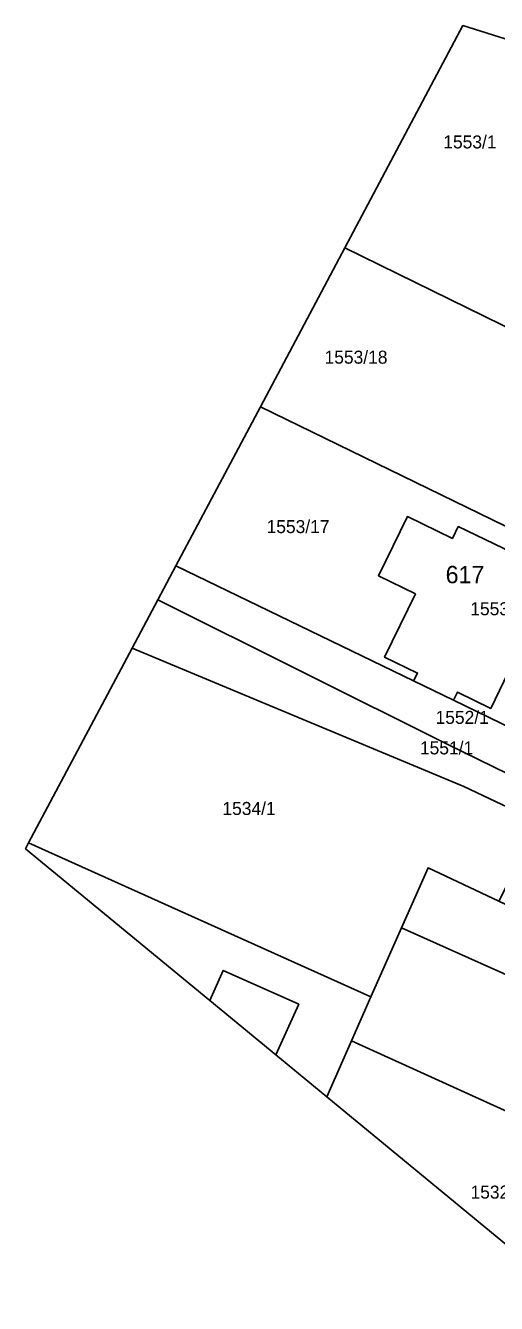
# Model space of a CAD drawing. Extents: x -559813 to -559493, y -1075874 to -1075701.
# Drawn here: x -559812.9 to -559758.6, y -1075848.7 to -1075701.4 of the extents above; entities that cross this region are included whole.
import ezdxf

# ---------------------------------------------------------------- set-up
doc = ezdxf.new("R2010")
doc.units = 0
for name, color, linetype in [('Adresní místo-text', 7, 'Continuous'), ('Parcela-polygon', 7, 'Continuous'), ('Parcela-text', 7, 'Continuous')]:
    doc.layers.add(name, color=color, linetype=linetype)

msp = doc.modelspace()

# ---------------------------------------------------------------- linework, layer by layer
at = {"layer": 'Parcela-polygon'}
for p, q in [((-559776.1, -1075727), (-559785.83, -1075745.32)), ((-559785.83, -1075745.32), (-559795.59, -1075763.68)), ((-559795.59, -1075763.68), (-559797.67, -1075767.59)), ((-559797.67, -1075767.59), (-559800.61, -1075773.14)), ((-559800.61, -1075773.14), (-559812.55, -1075795.61)), ((-559791.68, -1075813.75), (-559784.05, -1075820.04)), ((-559784.05, -1075820.04), (-559778.19, -1075824.87)), ((-559778.19, -1075824.87), (-559749.28, -1075848.69))]:
    msp.add_line(p, q, dxfattribs=at)
for points in [[(-559733.58, -1075710.47), (-559762.5, -1075701.39), (-559776.1, -1075727)], [(-559776.1, -1075727), (-559731.8, -1075748.76), (-559730.08, -1075745.15), (-559717.64, -1075718.96), (-559733.14, -1075710.71), (-559733.58, -1075710.47)], [(-559785.83, -1075745.32), (-559747.18, -1075764.18), (-559737.76, -1075760.91), (-559731.8, -1075748.76), (-559776.1, -1075727)], [(-559795.59, -1075763.68), (-559768.2, -1075776.93), (-559767.73, -1075776.03), (-559771.54, -1075774.2), (-559767.99, -1075766.9), (-559772.22, -1075764.81), (-559768.9, -1075757.99), (-559763.72, -1075760.51), (-559763.04, -1075759.14), (-559751.73, -1075764.6), (-559753.61, -1075768.39), (-559752.72, -1075768.82), (-559754.91, -1075773.41), (-559755.83, -1075772.92), (-559759.31, -1075780.1), (-559763.15, -1075778.22), (-559763.6, -1075779.15), (-559749.98, -1075785.74), (-559743.97, -1075773.56), (-559747.18, -1075764.18), (-559785.83, -1075745.32)], [(-559797.67, -1075767.59), (-559764.23, -1075784.25), (-559752.15, -1075790.16), (-559749.98, -1075785.74), (-559763.6, -1075779.15), (-559768.2, -1075776.93), (-559795.59, -1075763.68)], [(-559800.61, -1075773.14), (-559762.4, -1075789.09), (-559753.71, -1075793.22), (-559752.15, -1075790.16), (-559764.23, -1075784.25), (-559797.67, -1075767.59)], [(-559812.55, -1075795.61), (-559773.1, -1075813.33), (-559769.59, -1075805.38), (-559766.53, -1075798.46), (-559758.36, -1075802.33), (-559753.71, -1075793.22), (-559762.4, -1075789.09), (-559800.61, -1075773.14)], [(-559812.55, -1075795.61), (-559812.9, -1075796.28), (-559791.68, -1075813.75)], [(-559778.19, -1075824.87), (-559775.35, -1075818.43), (-559773.1, -1075813.33), (-559812.55, -1075795.61)], [(-559791.68, -1075813.75), (-559790.13, -1075810.29), (-559781.43, -1075814.2), (-559784.05, -1075820.04)], [(-559784.05, -1075820.04), (-559781.43, -1075814.2), (-559790.13, -1075810.29), (-559791.68, -1075813.75)], [(-559749.28, -1075848.69), (-559748.24, -1075846.45), (-559755.02, -1075843.27), (-559749.7, -1075831.92), (-559742.95, -1075835.07), (-559742.2, -1075833.46), (-559775.35, -1075818.43), (-559778.19, -1075824.87)]]:
    msp.add_lwpolyline(points, dxfattribs=at)
for points in [[(-559763.72, -1075760.51), (-559768.9, -1075757.99), (-559772.22, -1075764.81), (-559767.99, -1075766.9), (-559771.54, -1075774.2), (-559767.73, -1075776.03), (-559768.2, -1075776.93), (-559763.6, -1075779.15), (-559763.15, -1075778.22), (-559759.31, -1075780.1), (-559755.83, -1075772.92), (-559754.91, -1075773.41), (-559752.72, -1075768.82), (-559753.61, -1075768.39), (-559751.73, -1075764.6), (-559763.04, -1075759.14)], [(-559752.88, -1075812.71), (-559754.47, -1075811.8), (-559753.84, -1075810.76), (-559752.51, -1075811.55), (-559751.19, -1075812.16), (-559749.74, -1075812.64), (-559750.1, -1075813.77), (-559751.85, -1075813.14), (-559751.91, -1075813.31), (-559743.83, -1075816.93), (-559747.51, -1075825.13), (-559739.88, -1075828.47), (-559742.2, -1075833.46), (-559731.69, -1075838.23), (-559722.85, -1075819.18), (-559758.36, -1075802.33), (-559766.53, -1075798.46), (-559769.59, -1075805.38), (-559760.42, -1075809.49), (-559752.91, -1075812.86)], [(-559760.42, -1075809.49), (-559769.59, -1075805.38), (-559773.1, -1075813.33), (-559775.35, -1075818.43), (-559742.2, -1075833.46), (-559739.88, -1075828.47), (-559747.51, -1075825.13), (-559743.83, -1075816.93), (-559751.91, -1075813.31), (-559751.85, -1075813.14), (-559750.1, -1075813.77), (-559749.74, -1075812.64), (-559751.19, -1075812.16), (-559752.51, -1075811.55), (-559753.84, -1075810.76), (-559754.47, -1075811.8), (-559752.88, -1075812.71), (-559752.91, -1075812.86)]]:
    msp.add_lwpolyline(points, close=True, dxfattribs=at)

# ---------------------------------------------------------------- texts
at = {"layer": 'Adresní místo-text'}
msp.add_text('617', height=2, dxfattribs=at).set_placement((-559764.5, -1075765.67))
at = {"layer": 'Parcela-text'}
for s, p in [('1553/1', (-559764.77, -1075715.55)), ('1553/18', (-559778.45, -1075740.36)), ('1553/17', (-559785.13, -1075759.89)), ('1553/32', (-559761.66, -1075769.36)), ('1552/1', (-559765.66, -1075781.88)), ('1551/1', (-559767.46, -1075785.4)), ('1534/1', (-559790.22, -1075792.38)), ('1532/2', (-559761.63, -1075836.6))]:
    msp.add_text(s, height=1.5, dxfattribs=at).set_placement(p)

doc.saveas('drawing.dxf')
